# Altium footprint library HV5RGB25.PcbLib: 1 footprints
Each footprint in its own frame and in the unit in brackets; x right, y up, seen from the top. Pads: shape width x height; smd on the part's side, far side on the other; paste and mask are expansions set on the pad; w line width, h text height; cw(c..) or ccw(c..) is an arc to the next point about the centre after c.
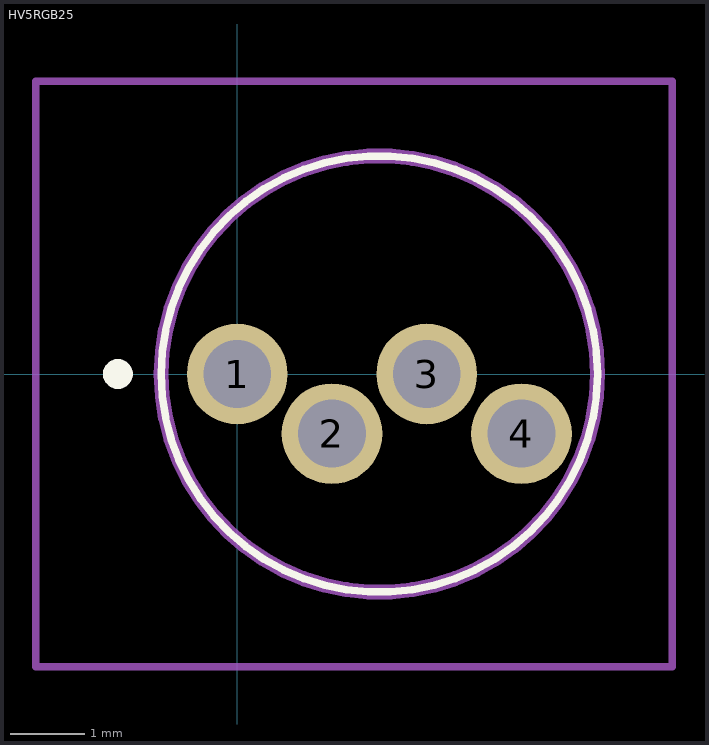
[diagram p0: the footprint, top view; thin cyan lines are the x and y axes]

## HV5RGB25 [mm]
pads (4):
  round 1.35 hole 0.91: 1(0,0) 2(1.27,-0.8) 3(2.54,0) 4(3.81,-0.8)
Top Overlay:
  lines w0.1: -1.02,0 -1.02,0 ; -1.02,0 cw(c1.905,0) 4.83,0 ; -1.02,0 ccw(c1.905,0) 4.83,0 ; 4.83,0 4.83,0
  lines w0.2: -1.6,-0.1 ccw(c-1.6,0) -1.6,0.1 ; -1.6,-0.1 -1.6,-0.1 ; -1.6,-0.1 cw(c-1.6,0) -1.6,0.1 ; -1.6,0.1 -1.6,0.1
Mechanical 15:
  lines w0.2: -1.02,0 -1.02,0 ; -1.02,0 cw(c1.905,0) 4.83,0 ; -1.02,0 ccw(c1.905,0) 4.83,0 ; 4.83,0 4.83,0
Mechanical 20:
  lines w0.1: -2.7,-3.925 5.83,-3.925 5.83,3.925 -2.7,3.925 -2.7,-3.925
